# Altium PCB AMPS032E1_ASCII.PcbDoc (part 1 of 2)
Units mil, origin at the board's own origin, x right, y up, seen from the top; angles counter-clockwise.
Board outline 1650 x 2660 mil, 4 copper layers (Top Layer L1, GND Plane L2, VCC/VEE Plane L3, Bottom Layer L4), stack 61.6 mil thick; 53 components, 15 nets, 89 pads, 109 vias.
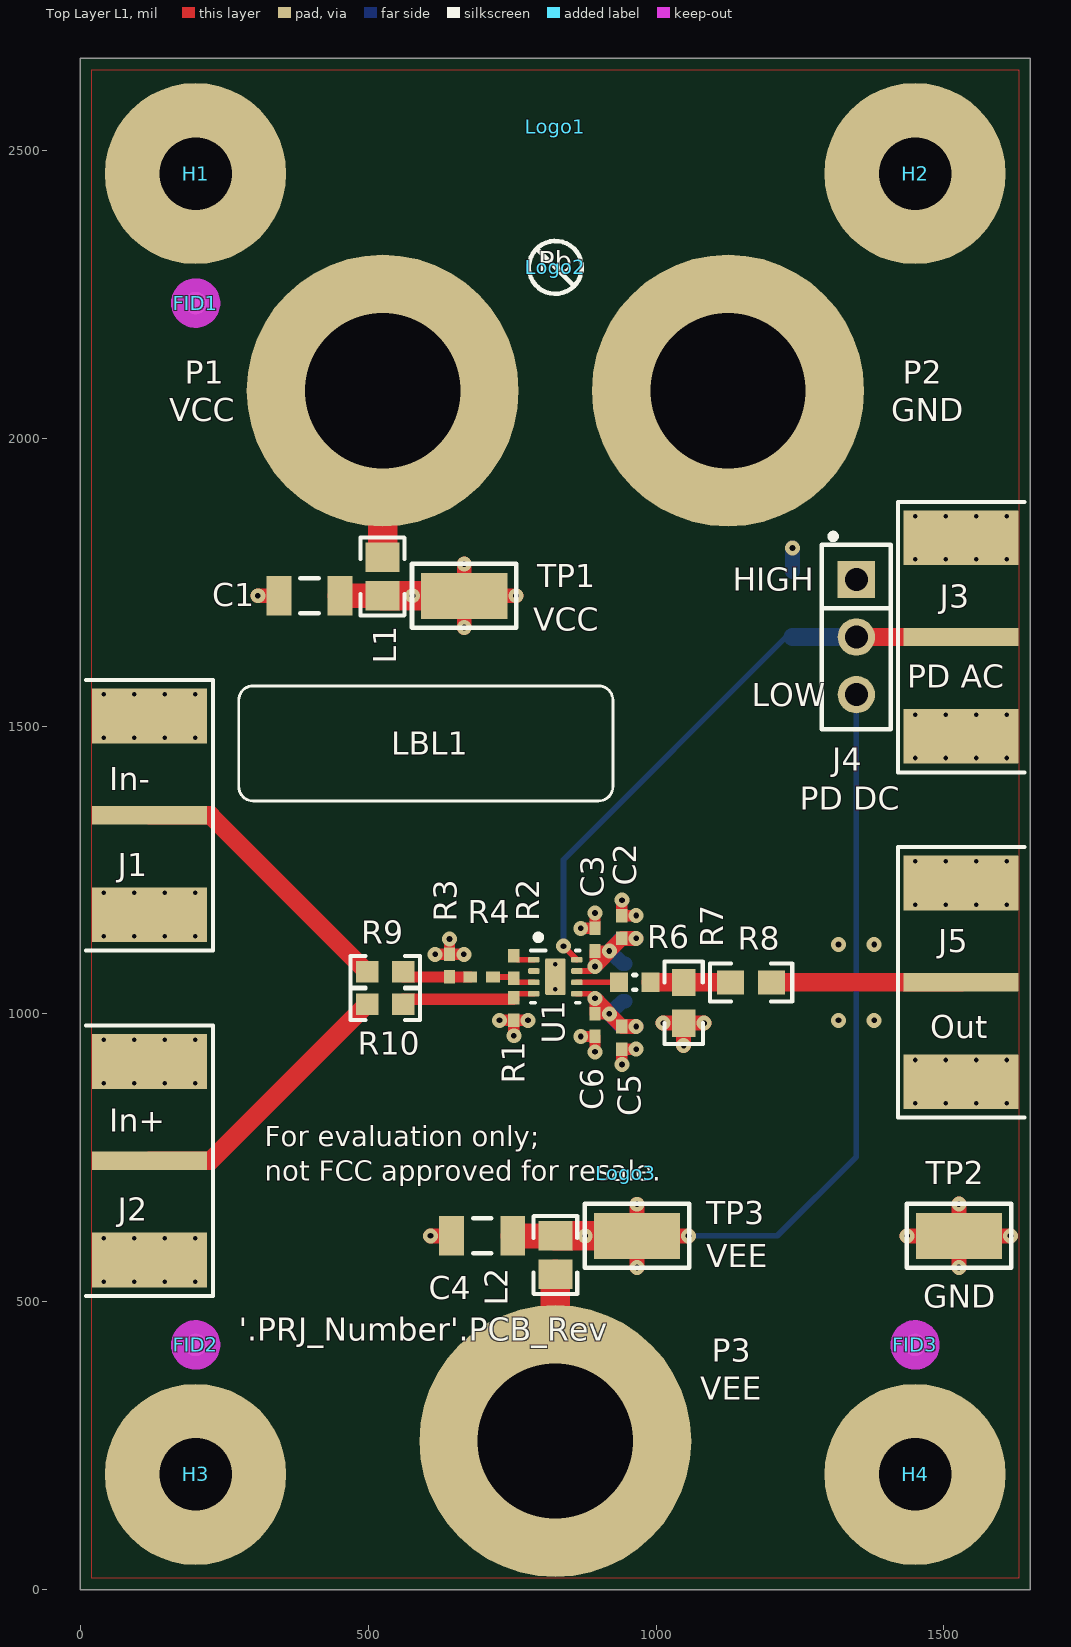
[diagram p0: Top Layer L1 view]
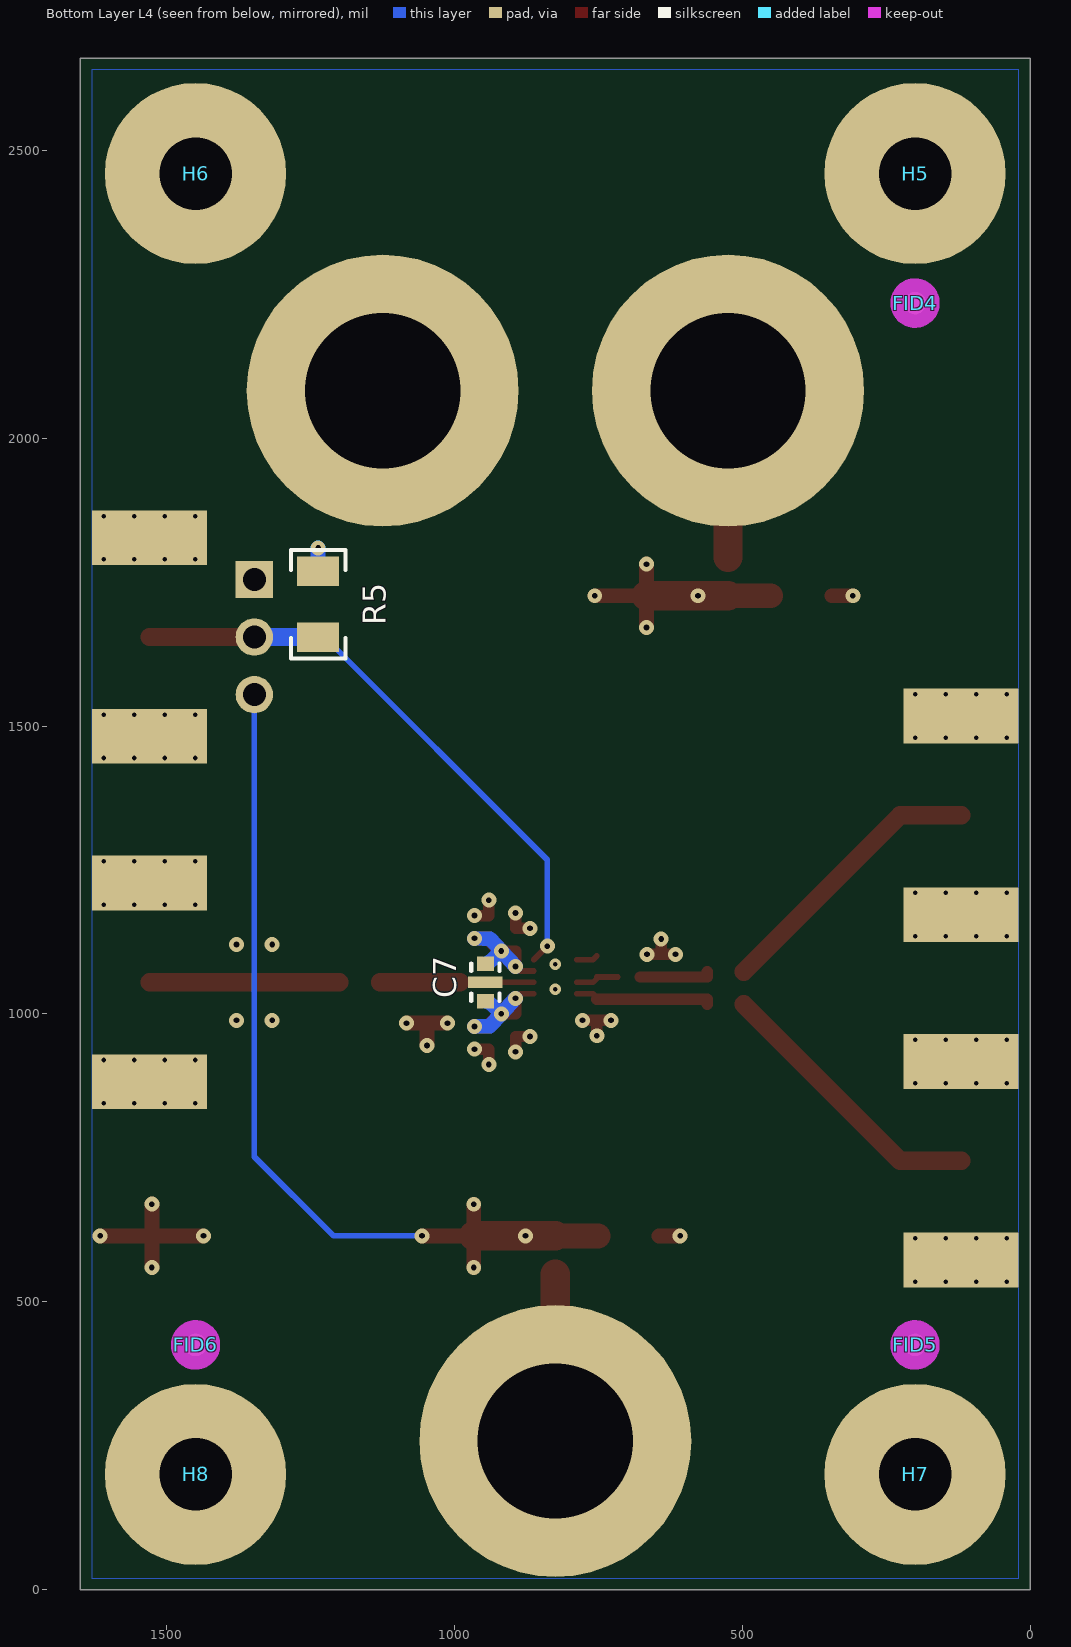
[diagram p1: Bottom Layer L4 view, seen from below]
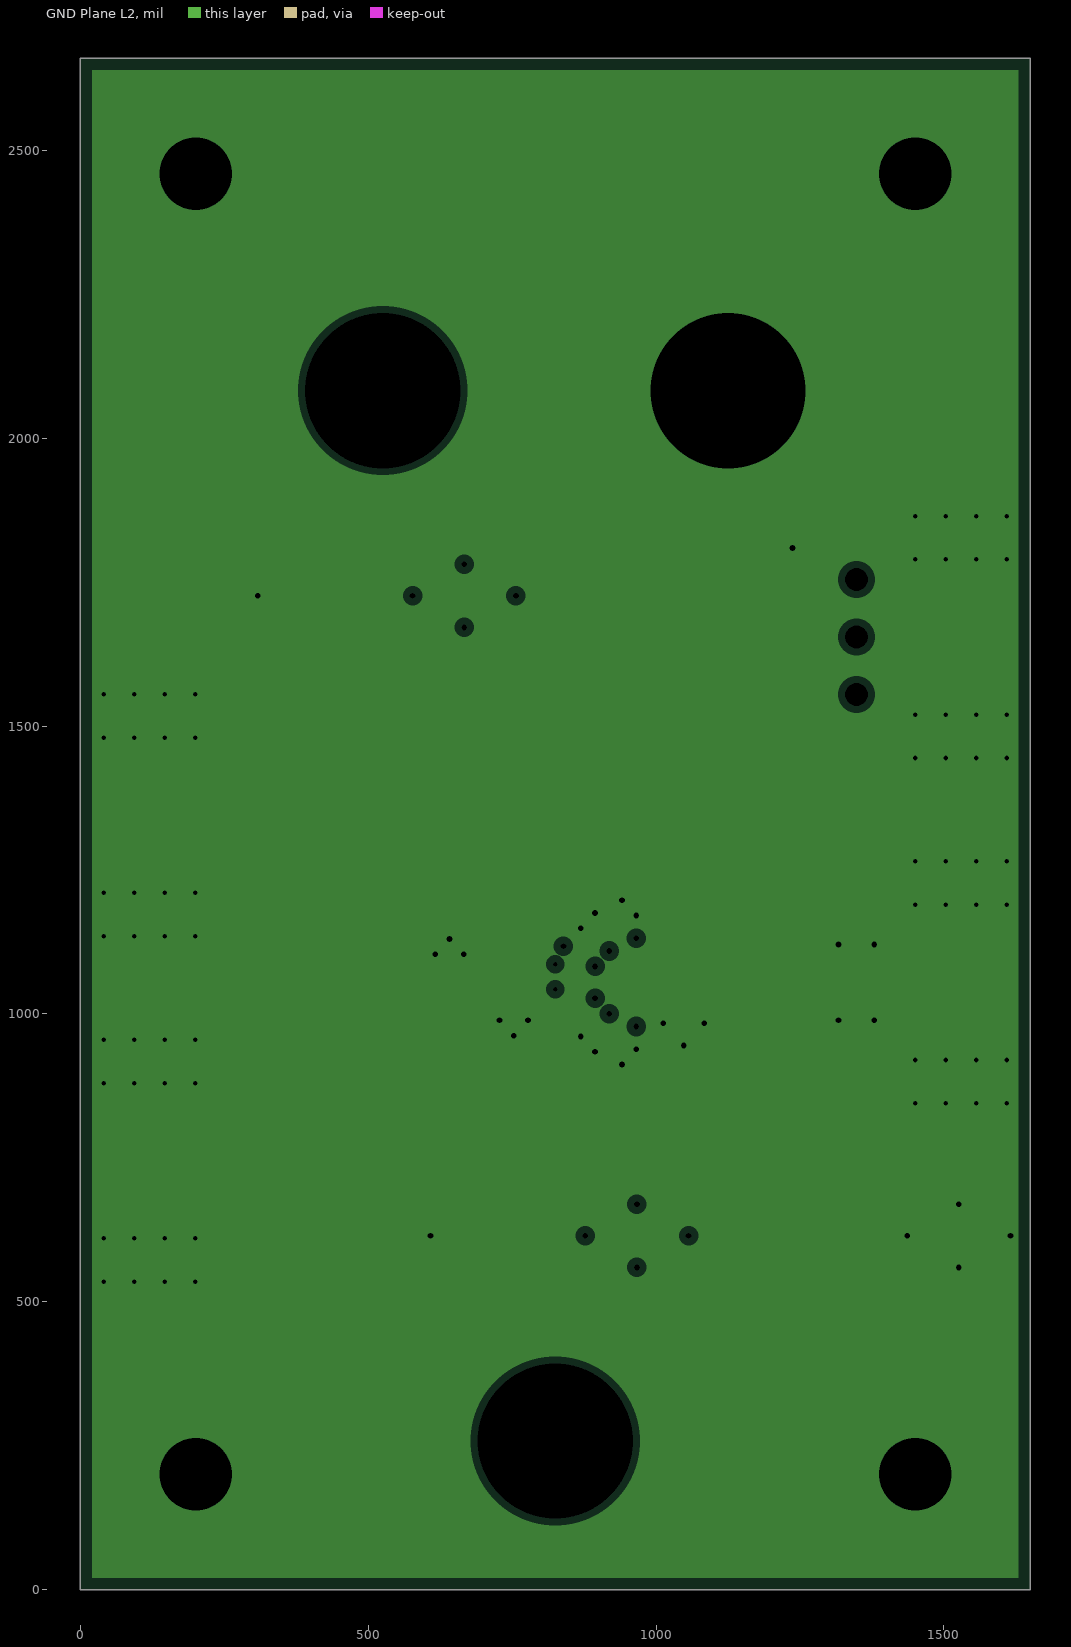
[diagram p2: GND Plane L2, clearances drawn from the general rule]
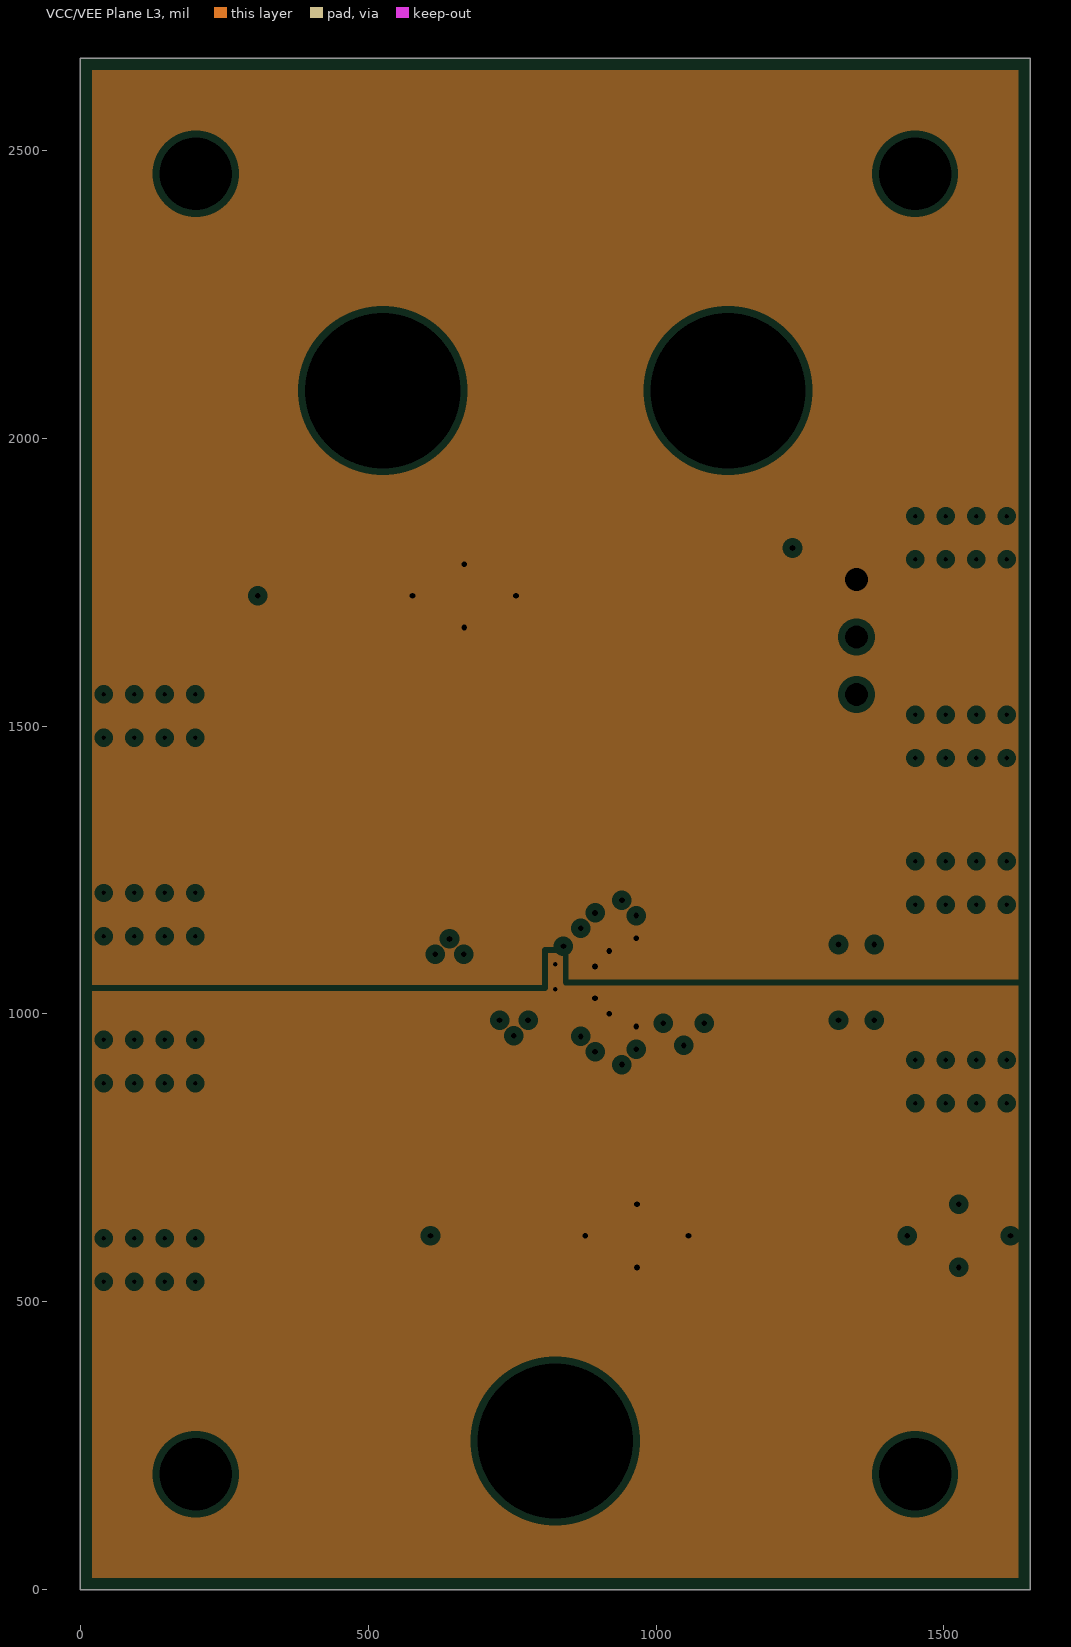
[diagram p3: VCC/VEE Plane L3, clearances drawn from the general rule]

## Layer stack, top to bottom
Top Solder: solder mask 0.4, Solder Resist, Dk 3.5
Top Layer L1: signal copper 1.4
Dielectric 1: core 15, FR408HR, Dk 3.8
GND Plane L2: plane copper 1.4, net GND
Dielectric 2: prepreg 26, FR-4 High Tg, Dk 4.6
VCC/VEE Plane L3: plane copper 1.4, net (Multiple Nets)
Dielectric 3: core 15, FR-4 High Tg, Dk 4.6
Bottom Layer L4: signal copper 1.4
Bottom Solder: solder mask 0.4, Solder Resist, Dk 3.5

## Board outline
0,0 1650,0 1650,2660 0,2660

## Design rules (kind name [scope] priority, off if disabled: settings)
AcuteAngle [All] p0: scope1count=1 scope1_0_kind=Board scope1_0_value=Board scope2count=1 scope2_0_kind=Board scope2_0_value=Board commentlength=0 minimum=4.50000000000000E+0001
AcuteAngle [All] p1: minimum=4.50000000000000E+0001 checktracksonly=FALSE
AssemblyTestPointUsage [All] p0: scope1count=1 scope1_0_kind=Board scope1_0_value=Board scope2count=1 scope2_0_kind=Board scope2_0_value=Board commentlength=0
AssemblyTestPointUsage [All] p1: valid=2
AssemblyTestpoint [All] p0: scope1count=1 scope1_0_kind=Board scope1_0_value=Board scope2count=1 scope2_0_kind=Board scope2_0_value=Board commentlength=0
BoardOutlineClearance BoardOutlineClearance_MountingHoles [All] p0 off: scope1count=1 scope1_0_kind=Board scope1_0_value=Board scope2count=1 scope2_0_kind=Board scope2_0_value=Board commentlength=86 gap=40 // Protel DXP Scope 1 Expression Was: OnCopper and InComponentClass('Mounting Holes')
BoardOutlineClearance BoardOutlineClearance_Poly [All] p0 off: scope1count=1 scope1_0_kind=Board scope1_0_value=Board scope2count=1 scope2_0_kind=Board scope2_0_value=Board commentlength=58 gap=20 // Protel DXP Scope 1 Expression Was: OnCopper and IsPoly
BoardOutlineClearance [All] p0 off: scope1count=1 scope1_0_kind=Board scope1_0_value=Board scope2count=1 scope2_0_kind=Board scope2_0_value=Board commentlength=172 gap=20 // Protel DXP Scope 1 Expression Was: OnCopper and Not InComponentClass('Logo') and not InComponentClass('FiducialMark') and not InRegion(1000,500,4000,800) and not InPoly
BoardOutlineClearance BoardOutlineClearance_MountingHoles [OnCopper and InComponentClass('Mounting Holes')] p1: gap=40 ignorepadtopadclearanceinfootprint=FALSE
BoardOutlineClearance BoardOutlineClearance_Poly [OnCopper and IsPoly] p2: gap=20 ignorepadtopadclearanceinfootprint=FALSE
BoardOutlineClearance [OnCopper and Not InComponentClass('Logo') and not InComponentClass('FiducialMark') and not InRegion(1000,500,4000,800) and not InPoly] p3: gap=20 ignorepadtopadclearanceinfootprint=FALSE
Clearance Clearance_FiducialMark [All] p0 off: scope1count=1 scope1_0_kind=Board scope1_0_value=Board scope2count=1 scope2_0_kind=Board scope2_0_value=Board commentlength=81 gap=0 // Protel DXP Scope 2 Expression Was: IsPad and InComponentClass('FiducialMark')
Clearance Clearance_1 [All] p0 off: scope1count=1 scope1_0_kind=Board scope1_0_value=Board scope2count=1 scope2_0_kind=Board scope2_0_value=Board commentlength=137 gap=35 // Protel DXP Scope 2 Expression Was: (InNet('NetJ1_1') OR InNet('NetJ2_1') OR InNet('NetJ4_2') OR InNet('NetJ5_1') OR InNet('NetR6_*'))
Clearance Clearance_Keepouts [All] p0 off: scope1count=1 scope1_0_kind=Board scope1_0_value=Board scope2count=1 scope2_0_kind=Board scope2_0_value=Board commentlength=99 gap=0 // Protel DXP Scope 2 Expression Was: ((IsTrack Or IsArc) And Not InPoly) And IsFree and IsKeepOut
Clearance Clearance_Poly [All] p0 off: scope1count=1 scope1_0_kind=Board scope1_0_value=Board scope2count=1 scope2_0_kind=Board scope2_0_value=Board commentlength=48 gap=13 // Protel DXP Scope 1 Expression Was: InPolygon
Clearance [All] p0: scope1count=1 scope1_0_kind=Board scope1_0_value=Board scope2count=1 scope2_0_kind=Board scope2_0_value=Board commentlength=0 gap=7.87
Clearance Clearance_FiducialMark [IsKeepOut and InComponentClass('FiducialMark') vs IsPad and InComponentClass('FiducialMark')] p1: gap=0 ignorepadtopadclearanceinfootprint=FALSE
Clearance Clearance_1 [(InNamedPolygon('Top Layer L1-GND')) vs (InNet('NetJ1_1') OR InNet('NetJ2_1') OR InNet('NetJ4_2') OR InNet('NetJ5_1') OR InNet('NetR6_*'))] p2: gap=35 ignorepadtopadclearanceinfootprint=FALSE except(0: Arc-Hole Track-Hole SMDPad-Hole THPad-Hole Via-Hole Fill-Hole Poly-Hole Region-Hole Text-Hole)
Clearance Clearance_Keepouts [((IsTrack Or IsArc) And Not InPoly) And IsFree and IsKeepOut vs ((IsTrack Or IsArc) And Not InPoly) And IsFree and IsKeepOut] p3: gap=0 ignorepadtopadclearanceinfootprint=FALSE
Clearance Clearance_Poly [InPolygon] p4: gap=13 ignorepadtopadclearanceinfootprint=FALSE except(0: Arc-Hole Track-Hole SMDPad-Hole THPad-Hole Via-Hole Fill-Hole Poly-Hole Region-Hole Text-Hole)
Clearance [All] p5: gap=7.87 ignorepadtopadclearanceinfootprint=FALSE except(0: Arc-Hole Track-Hole SMDPad-Hole THPad-Hole Via-Hole Fill-Hole Poly-Hole Region-Hole Text-Hole)
ComponentClearance ComponentClearance_MountingHoles_FiducialMarks [All] p0: scope1count=1 scope1_0_kind=ComponentClass scope1_0_value="Mounting Holes" scope2count=1 scope2_0_kind=ComponentClass scope2_0_value=FiducialMark commentlength=0 gap=50 collisioncheckmode=3
ComponentClearance ComponentClearance_Shunt [All] p0: scope1count=1 scope1_0_kind=ComponentClass scope1_0_value=Header scope2count=1 scope2_0_kind=ComponentClass scope2_0_value=Shunt commentlength=0 gap=0 collisioncheckmode=3
ComponentClearance ComponentClearance_Logo [All] p0: scope1count=1 scope1_0_kind=ComponentClass scope1_0_value=Logo scope2count=1 scope2_0_kind=Board scope2_0_value=Board commentlength=0 gap=50 collisioncheckmode=3
ComponentClearance ComponentClearance_ScrewToNut [All] p0 off: scope1count=1 scope1_0_kind=Board scope1_0_value=Board scope2count=1 scope2_0_kind=Board scope2_0_value=Board commentlength=71 gap=5 collisioncheckmode=3 // Protel DXP Scope 2 Expression Was: (HasFootprint('Keystone_1902C'))
ComponentClearance ComponentClearance_MountingHoles [All] p0: scope1count=1 scope1_0_kind=ComponentClass scope1_0_value="Mounting Holes" scope2count=1 scope2_0_kind=Board scope2_0_value=Board commentlength=0 gap=100 collisioncheckmode=3
ComponentClearance ComponentClearance_SmallPassives [All] p0 off: scope1count=1 scope1_0_kind=Board scope1_0_value=Board scope2count=1 scope2_0_kind=Board scope2_0_value=Board commentlength=536 gap=14.96 collisioncheckmode=3 // Protel DXP Scope 2 Expression Was: HasFootprint('0201*') or HasFootprint('0402*') or HasFootprint('0508') or HasFootprint('0603*') or HasFootprint('0612') or HasFootprint('0805*') or HasFootprint('0815*') or HasFootprint('0830*') or HasFootprint('1206*') or HasFootprint('1210*') or HasFootprint('1808*') or HasFootprint('1812*') or HasFootprint('1825*') or HasFootprint('2010*') or HasFootprint('2220*') or HasFootprint('2225*') or HasFootprint('2512*') or HasFootprint('2728*') or HasFootprint('3518*') or HasFootprint('DSG0008A')
ComponentClearance ComponentClearance_THtoSMT [All] p0 off: scope1count=1 scope1_0_kind=Board scope1_0_value=Board scope2count=1 scope2_0_kind=Board scope2_0_value=Board commentlength=53 gap=25 collisioncheckmode=3 // Protel DXP Scope 2 Expression Was: IsSMTComponent
ComponentClearance ComponentClearance_THtoTH [All] p0 off: scope1count=1 scope1_0_kind=Board scope1_0_value=Board scope2count=1 scope2_0_kind=Board scope2_0_value=Board commentlength=54 gap=30 collisioncheckmode=3 // Protel DXP Scope 2 Expression Was: IsThruComponent
ComponentClearance [All] p0: scope1count=1 scope1_0_kind=Board scope1_0_value=Board scope2count=1 scope2_0_kind=Board scope2_0_value=Board commentlength=0 gap=30 collisioncheckmode=3
ComponentClearance ComponentClearance_C8_R10 [All] p0 off: scope1count=1 scope1_0_kind=Board scope1_0_value=Board scope2count=1 scope2_0_kind=Board scope2_0_value=Board commentlength=80 gap=0 collisioncheckmode=3 // Protel DXP Scope 2 Expression Was: (InComponent('C8') OR InComponent('R10'))
ComponentClearance ComponentClearance_C9_R11 [All] p0 off: scope1count=1 scope1_0_kind=Board scope1_0_value=Board scope2count=1 scope2_0_kind=Board scope2_0_value=Board commentlength=80 gap=0 collisioncheckmode=3 // Protel DXP Scope 2 Expression Was: (InComponent('C9') OR InComponent('R11'))
ComponentClearance ComponentClearance_C8_R10 [(InComponent('C8') OR InComponent('R10')) vs (InComponent('C8') OR InComponent('R10'))] p1: gap=0 collisioncheckmode=3 verticalgap=0 showdistances=FALSE
ComponentClearance ComponentClearance_C9_R11 [(InComponent('C9') OR InComponent('R11')) vs (InComponent('C9') OR InComponent('R11'))] p2: gap=0 collisioncheckmode=3 verticalgap=0 showdistances=FALSE
ComponentClearance ComponentClearance_MountingHoles_FiducialMarks [InComponentClass('Mounting Holes') vs InComponentClass('FiducialMark')] p3: gap=50 collisioncheckmode=3 verticalgap=10 showdistances=FALSE
ComponentClearance ComponentClearance_Shunt [InComponentClass('Header') vs InComponentClass('Shunt')] p4: gap=0 collisioncheckmode=3 verticalgap=0 showdistances=FALSE
ComponentClearance ComponentClearance_Logo [InComponentClass('Logo')] p5: gap=50 collisioncheckmode=3 verticalgap=10 showdistances=FALSE
ComponentClearance ComponentClearance_ScrewToNut [(HasFootprint('NY PMS 440 0025 PH')) vs (HasFootprint('Keystone_1902C'))] p6: gap=5 collisioncheckmode=3 verticalgap=10 showdistances=FALSE
ComponentClearance ComponentClearance_MountingHoles [InComponentClass('Mounting Holes')] p7: gap=100 collisioncheckmode=3 verticalgap=100000 showdistances=FALSE
ComponentClearance ComponentClearance_SmallPassives [HasFootprint('0201*') or HasFootprint('0402*') or HasFootprint('0508') or HasFootprint('0603*') or HasFootprint('0612') or HasFootprint('0805*') or HasFootprint('0815*') or HasFootprint('0830*') or HasFootprint('1206*') or HasFootprint('1210*') or HasFootprint('1808*') or HasFootprint('1812*') or HasFootprint('1825*') or HasFootprint('2010*') or HasFootprint('2220*') or HasFootprint('2225*') or HasFootprint('2512*') or HasFootprint('2728*') or HasFootprint('3518*') or HasFootprint('DSG0008A') vs HasFootprint('0201*') or HasFootprint('0402*') or HasFootprint('0508') or HasFootprint('0603*') or HasFootprint('0612') or HasFootprint('0805*') or HasFootprint('0815*') or HasFootprint('0830*') or HasFootprint('1206*') or HasFootprint('1210*') or HasFootprint('1808*') or HasFootprint('1812*') or HasFootprint('1825*') or HasFootprint('2010*') or HasFootprint('2220*') or HasFootprint('2225*') or HasFootprint('2512*') or HasFootprint('2728*') or HasFootprint('3518*') or HasFootprint('DSG0008A')] p8: gap=14.96 collisioncheckmode=3 verticalgap=10 showdistances=FALSE
ComponentClearance ComponentClearance_THtoSMT [IsThruComponent vs IsSMTComponent] p9: gap=25 collisioncheckmode=3 verticalgap=30 showdistances=FALSE
ComponentClearance ComponentClearance_THtoTH [IsThruComponent vs IsThruComponent] p10: gap=30 collisioncheckmode=3 verticalgap=30 showdistances=FALSE
ComponentClearance [All] p11: gap=30 collisioncheckmode=3 verticalgap=10 showdistances=FALSE
DiffPairsRouting [All] p0: scope1count=1 scope1_0_kind=Board scope1_0_value=Board scope2count=1 scope2_0_kind=Board scope2_0_value=Board commentlength=0
DiffPairsRouting [All] p1: maxlimit=100 minlimit=10 mostfreqgap=10 toplayer_minwidth=15 toplayer_maxwidth=15 toplayer_prefwidth=15 bottomlayer_minwidth=15 bottomlayer_maxwidth=15 bottomlayer_prefwidth=15 maxuncoupledlength=1000
FabricationTestPointUsage TestPointUsage [All] p0: scope1count=1 scope1_0_kind=Board scope1_0_value=Board scope2count=1 scope2_0_kind=Board scope2_0_value=Board commentlength=0 valid=2 allowmultiple=FALSE
FabricationTestPointUsage TestPointUsage [All] p1: valid=2 allowmultiple=FALSE
FabricationTestpoint Testpoint [All] p0: scope1count=1 scope1_0_kind=Board scope1_0_value=Board scope2count=1 scope2_0_kind=Board scope2_0_value=Board commentlength=0 side=3 testpointundercomponent=TRUE minsize=40 maxsize=100 preferedsize=60 minholesize=0 maxholesize=40 preferedholesize=32 testpointgrid=1
FabricationTestpoint Testpoint [All] p1: side=3 testpointundercomponent=TRUE minsize=40 maxsize=100 preferedsize=60 minholesize=0 maxholesize=40 preferedholesize=32 testpointgrid=1 allowsidetop=TRUE allowsidebottom=TRUE usegrid=TRUE gridtolerance=0.01
FanoutControl Fanout_LCC [All] p0 off: scope1count=1 scope1_0_kind=Board scope1_0_value=Board scope2count=1 scope2_0_kind=Board scope2_0_value=Board commentlength=69 // Protel DXP Scope 1 Expression Was: IsLCC   Fanout_LCC (Default Rule)
FanoutControl Fanout_BGA [All] p0 off: scope1count=1 scope1_0_kind=Board scope1_0_value=Board scope2count=1 scope2_0_kind=Board scope2_0_value=Board commentlength=69 // Protel DXP Scope 1 Expression Was: IsBGA   Fanout_BGA (Default Rule)
FanoutControl Fanout_SOIC [All] p0 off: scope1count=1 scope1_0_kind=Board scope1_0_value=Board scope2count=1 scope2_0_kind=Board scope2_0_value=Board commentlength=71 // Protel DXP Scope 1 Expression Was: IsSOIC   Fanout_SOIC (Default Rule)
FanoutControl Fanout_Default [All] p0: scope1count=1 scope1_0_kind=Board scope1_0_value=Board scope2count=1 scope2_0_kind=Board scope2_0_value=Board commentlength=30 // Fanout_Default (Default Rule)
FanoutControl Fanout_Small [All] p0 off: scope1count=1 scope1_0_kind=Board scope1_0_value=Board scope2count=1 scope2_0_kind=Board scope2_0_value=Board commentlength=84 // Protel DXP Scope 1 Expression Was: (CompPinCount < 5)   Fanout_Small (Default Rule)
FanoutControl Fanout_LCC [IsLCC] p1: bgadir=Out bgaviamode=Centered fanoutstyle=Auto fanoutdirection=Alternating viagrid=1 // Fanout_LCC (Default Rule)
FanoutControl Fanout_BGA [IsBGA] p2: bgadir=Out bgaviamode=Centered fanoutstyle=Auto fanoutdirection=Alternating viagrid=1 // Fanout_BGA (Default Rule)
FanoutControl Fanout_Default [All] p4: bgadir=Out bgaviamode=Centered fanoutstyle=Auto fanoutdirection=Alternating viagrid=1 // Fanout_Default (Default Rule)
FanoutControl Fanout_Small [(CompPinCount < 5)] p5: bgadir=Out bgaviamode=Centered fanoutstyle=Auto fanoutdirection=OutThenIn viagrid=1 // Fanout_Small (Default Rule)
Height Height_D1 [All] p0: scope1count=1 scope1_0_kind=Component scope1_0_value=D1 scope2count=1 scope2_0_kind=Board scope2_0_value=Board commentlength=0
Height [All] p0: scope1count=1 scope1_0_kind=Board scope1_0_value=Board scope2count=1 scope2_0_kind=Board scope2_0_value=Board commentlength=0
Height Height_D1 [InComponent('D1')] p1: minheight=0 maxheight=1079 prefheight=500
Height [All] p2: minheight=0 maxheight=1000 prefheight=500
HoleSize [All] p0: scope1count=1 scope1_0_kind=Board scope1_0_value=Board scope2count=1 scope2_0_kind=Board scope2_0_value=Board commentlength=0 absolutevalues=TRUE maxlimit=270 minlimit=7.87 maxpercent=80.000 minpercent=20.000
HoleSize [All] p1: absolutevalues=TRUE maxlimit=270 minlimit=7.87 maxpercent=80.000 minpercent=20.000
HoleToHoleClearance [All] p0: scope1count=1 scope1_0_kind=Board scope1_0_value=Board scope2count=1 scope2_0_kind=Board scope2_0_value=Board commentlength=0
LayerPairs [All] p0: scope1count=1 scope1_0_kind=Board scope1_0_value=Board scope2count=1 scope2_0_kind=Board scope2_0_value=Board commentlength=0 enforce=TRUE
MinimumAnnularRing MinimumAnnularRing_1 [All] p0 off: scope1count=1 scope1_0_kind=Board scope1_0_value=Board scope2count=1 scope2_0_kind=Board scope2_0_value=Board commentlength=152 minimumring=5.91 // Protel DXP Scope 1 Expression Was: (InNamedUnion('Unions 9') or InNamedUnion('Unions 13') or InNamedUnion('Unions 14') or InNamedUnion('Unions 15'))
MinimumAnnularRing MinimumAnnularRing_ThermalPadVias [All] p0 off: scope1count=1 scope1_0_kind=Board scope1_0_value=Board scope2count=1 scope2_0_kind=Board scope2_0_value=Board commentlength=63 minimumring=5.91 // Protel DXP Scope 1 Expression Was: IsVia and InAnyComponent
MinimumAnnularRing [All] p0: scope1count=1 scope1_0_kind=Board scope1_0_value=Board scope2count=1 scope2_0_kind=Board scope2_0_value=Board commentlength=0 minimumring=8
MinimumAnnularRing MinimumAnnularRing_1 [(InNamedUnion('Unions 9') or InNamedUnion('Unions 13') or InNamedUnion('Unions 14') or InNamedUnion('Unions 15'))] p1: minimumring=5.91
MinimumAnnularRing MinimumAnnularRing_ThermalPadVias [IsVia and InAnyComponent] p2: minimumring=5.91
MinimumAnnularRing [All] p3: minimumring=8
MinimumSolderMaskSliver MinimumSolderMaskSliver_Logo [All] p0: scope1count=1 scope1_0_kind=ComponentClass scope1_0_value=Logo scope2count=1 scope2_0_kind=ComponentClass scope2_0_value=Logo commentlength=0
MinimumSolderMaskSliver [All] p0: scope1count=1 scope1_0_kind=Board scope1_0_value=Board scope2count=1 scope2_0_kind=Board scope2_0_value=Board commentlength=0
MinimumSolderMaskSliver MinimumSolderMaskSliver_Logo [InComponentClass('Logo') vs InComponentClass('Logo')] p1: minsoldermaskwidth=0.7
MinimumSolderMaskSliver [All] p2: minsoldermaskwidth=3.94
NetAntennae [All] p0: scope1count=1 scope1_0_kind=Board scope1_0_value=Board scope2count=1 scope2_0_kind=Board scope2_0_value=Board commentlength=0
PasteMaskExpansion [All] p0: scope1count=1 scope1_0_kind=Board scope1_0_value=Board scope2count=1 scope2_0_kind=Board scope2_0_value=Board commentlength=0 expansion=0
PlaneClearance [All] p0: scope1count=1 scope1_0_kind=Board scope1_0_value=Board scope2count=1 scope2_0_kind=Board scope2_0_value=Board commentlength=0 clearance=12
PlaneClearance [All] p1: clearance=12
PlaneConnect [All] p0: scope1count=1 scope1_0_kind=Board scope1_0_value=Board scope2count=1 scope2_0_kind=Board scope2_0_value=Board commentlength=0 planeconnectstyle=Direct reliefexpansion=10 reliefentries=4 reliefconductorwidth=10 reliefairgap=10
PlaneConnect [All] p1: planeconnectstyle=Direct reliefexpansion=10 reliefentries=4 reliefconductorwidth=10 reliefairgap=10
PolygonConnect [All] p0: scope1count=1 scope1_0_kind=Board scope1_0_value=Board scope2count=1 scope2_0_kind=Board scope2_0_value=Board commentlength=0 connectstyle=Direct reliefconductorwidth=25 reliefentries=4 polygonreliefangle="90 Angle"
PolygonConnect [All] p1: connectstyle=Direct reliefconductorwidth=25 reliefentries=4 polygonreliefangle="90 Angle" airgapwidth=10
RoutingCorners [All] p0: scope1count=1 scope1_0_kind=Board scope1_0_value=Board scope2count=1 scope2_0_kind=Board scope2_0_value=Board commentlength=0 cornerstyle=45-Degree minsetback=100 maxsetback=100
RoutingLayers [All] p0: scope1count=1 scope1_0_kind=Board scope1_0_value=Board scope2count=1 scope2_0_kind=Board scope2_0_value=Board commentlength=0 top layer=Automatic bottom layer=Automatic
RoutingPriority [All] p0: scope1count=1 scope1_0_kind=Board scope1_0_value=Board scope2count=1 scope2_0_kind=Board scope2_0_value=Board commentlength=0
RoutingTopology [All] p0: scope1count=1 scope1_0_kind=Board scope1_0_value=Board scope2count=1 scope2_0_kind=Board scope2_0_value=Board commentlength=0 topology=Shortest
RoutingVias RoutingVias_1 [All] p0 off: scope1count=1 scope1_0_kind=Board scope1_0_value=Board scope2count=1 scope2_0_kind=Board scope2_0_value=Board commentlength=152 holewidth=28 width=50 viastyle="Through Hole" minholewidth=7.87 minwidth=19.68 maxholewidth=28 maxwidth=50 // Protel DXP Scope 1 Expression Was: (InNamedUnion('Unions 9') or InNamedUnion('Unions 13') or InNamedUnion('Unions 14') or InNamedUnion('Unions 15'))
RoutingVias ThermalPadVias [All] p0 off: scope1count=1 scope1_0_kind=Board scope1_0_value=Board scope2count=1 scope2_0_kind=Board scope2_0_value=Board commentlength=63 holewidth=7.87 width=19.68 viastyle="Through Hole" minholewidth=7.87 minwidth=19.68 maxholewidth=12.99 maxwidth=23.62 // Protel DXP Scope 1 Expression Was: IsVia and InAnyComponent
RoutingVias [All] p0: scope1count=1 scope1_0_kind=Board scope1_0_value=Board scope2count=1 scope2_0_kind=Board scope2_0_value=Board commentlength=0 holewidth=16 width=34 viastyle="Through Hole" minholewidth=7.87 minwidth=26 maxholewidth=40 maxwidth=65
RoutingVias RoutingVias_1 [(InNamedUnion('Unions 9') or InNamedUnion('Unions 13') or InNamedUnion('Unions 14') or InNamedUnion('Unions 15'))] p1: holewidth=28 width=50 viastyle="Through Hole" minholewidth=7.87 minwidth=19.68 maxholewidth=28 maxwidth=50
RoutingVias ThermalPadVias [IsVia and InAnyComponent] p2: holewidth=7.87 width=19.68 viastyle="Through Hole" minholewidth=7.87 minwidth=19.68 maxholewidth=12.99 maxwidth=23.62
RoutingVias [All] p3: holewidth=16 width=34 viastyle="Through Hole" minholewidth=7.87 minwidth=26 maxholewidth=40 maxwidth=65
ShortCircuit [All] p0: scope1count=1 scope1_0_kind=Board scope1_0_value=Board scope2count=1 scope2_0_kind=Board scope2_0_value=Board commentlength=0 allowed=FALSE
SilkToBoardRegionClearance [All] p0 off: scope1count=1 scope1_0_kind=Board scope1_0_value=Board scope2count=1 scope2_0_kind=Board scope2_0_value=Board commentlength=130 // Protel DXP Scope 1 Expression Was: Not ((IsComment or IsDesignator) And (Hide <> 'False')) and not InRegion(1000,500,4000,800)
SilkToBoardRegionClearance [Not ((IsComment or IsDesignator) And (Hide <> 'False')) and not InRegion(1000,500,4000,800)] p1:
SilkToSilkClearance SilkToSilkClearance_Pb-FreeLogo [All] p0 off: scope1count=1 scope1_0_kind=Board scope1_0_value=Board scope2count=1 scope2_0_kind=Board scope2_0_value=Board commentlength=120 // Protel DXP Scope 2 Expression Was: (HasFootprint('Pb-Free_Overlay_Medium') OR HasFootprint('Pb-Free_Overlay_Small'))
SilkToSilkClearance [All] p0: scope1count=1 scope1_0_kind=Board scope1_0_value=Board scope2count=1 scope2_0_kind=Board scope2_0_value=Board commentlength=0
SilkToSilkClearance SilkToSilkClearance_Pb-FreeLogo [(HasFootprint('Pb-Free_Overlay_Medium') OR HasFootprint('Pb-Free_Overlay_Small')) vs (HasFootprint('Pb-Free_Overlay_Medium') OR HasFootprint('Pb-Free_Overlay_Small'))] p1: silktosilkclearance=0
SilkToSilkClearance [All] p2: silktosilkclearance=4
SilkToSolderMaskClearance SilkToComponentPadClearance [All] p0 off: scope1count=1 scope1_0_kind=Board scope1_0_value=Board scope2count=1 scope2_0_kind=Board scope2_0_value=Board commentlength=87 // Protel DXP Scope 1 Expression Was: (IsPad or IsFill or IsRegion) and InAnycomponent
SilkToSolderMaskClearance "Silk to Solder Mask Opening" [All] p0: scope1count=1 scope1_0_kind=Board scope1_0_value=Board scope2count=1 scope2_0_kind=Board scope2_0_value=Board commentlength=0
SilkToSolderMaskClearance SilkToComponentPadClearance [(IsPad or IsFill or IsRegion) and InAnycomponent] p1: minsilkscreentomaskgap=5 clearancetoexposedcopper=TRUE
SilkToSolderMaskClearance "Silk to Solder Mask Opening" [All] p2: minsilkscreentomaskgap=4 clearancetoexposedcopper=FALSE
SolderMaskExpansion [All] p0: scope1count=1 scope1_0_kind=Board scope1_0_value=Board scope2count=1 scope2_0_kind=Board scope2_0_value=Board commentlength=0 expansion=1.97
SolderMaskExpansion [All] p1: expansion=1.97
UnRoutedNet [All] p0: scope1count=1 scope1_0_kind=Board scope1_0_value=Board scope2count=1 scope2_0_kind=Board scope2_0_value=Board commentlength=0
UnpouredPolygon [All] p0: scope1count=1 scope1_0_kind=Board scope1_0_value=Board scope2count=1 scope2_0_kind=Board scope2_0_value=Board commentlength=0
Width [All] p0: scope1count=1 scope1_0_kind=Board scope1_0_value=Board scope2count=1 scope2_0_kind=Board scope2_0_value=Board commentlength=0 maxlimit=100 minlimit=6 preferedwidth=10
Width [All] p1: maxlimit=100 minlimit=6 preferedwidth=10 checkconnectedcopper=TRUE
13 further rules are at their usual default settings.

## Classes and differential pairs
component class Header: J4
component class Label: LBL1
component class AssemblyNote: ZZ1 ZZ2 ZZ3 ZZ4
component class FiducialMark: FID1 FID2 FID3 FID4 FID5 FID6
component class Logo: Logo1
component class "Mounting Holes": H1 H2 H3 H4

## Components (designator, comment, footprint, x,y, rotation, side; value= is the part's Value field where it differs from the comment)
C1 "GRM31MR71E225KA93L" 1206L 397.85,1726.53 r180 top
C2 "C1005X5R1E224M050BC" 0402L 940.63,1151.16 r90 top
C3 "GRM155R71E103KA01D" 0402L 894,1129.07 r90 top
C4 "GRM31MR71E225KA93L" 1206L 697.85,614.47 r0 top
C5 "C1005X5R1E224M050BC" 0402L 940.63,958.53 r90 top
C6 "GRM155R71E103KA01D" 0402L 894,980.61 r90 top
C7 "500X14W103MV4T" X2Y_0603 946.5,1054.84 r90 bottom
FID1 "Fiducial" Fiducial10-20 200,2235 r0 top
FID2 "Fiducial" Fiducial10-20 200,425 r0 top
FID3 "Fiducial" Fiducial10-20 1450,425 r0 top
FID4 "Fiducial" Fiducial10-20 200,2235 r0 bottom
FID5 "Fiducial" Fiducial10-20 200,425 r0 bottom
FID6 "Fiducial" Fiducial10-20 1450,425 r0 bottom
H1 "NY PMS 440 0025 PH" "NY PMS 440 0025 PH" 200,2460 r0 top locked
H2 "NY PMS 440 0025 PH" "NY PMS 440 0025 PH" 1450,2460 r0 top locked
H3 "NY PMS 440 0025 PH" "NY PMS 440 0025 PH" 200,200 r0 top locked
H4 "NY PMS 440 0025 PH" "NY PMS 440 0025 PH" 1450,200 r0 top locked
H5 "1902C" Keystone_1902C 200,2460 r180 bottom locked
H6 "1902C" Keystone_1902C 1450,2460 r180 bottom locked
H7 "1902C" Keystone_1902C 200,200 r180 bottom locked
H8 "1902C" Keystone_1902C 1450,200 r180 bottom locked
J1 "In-" Emerson_142-0701-851 10,1345 r90 top
J2 "In+" Emerson_142-0701-851 10,745 r90 top
J3 "PD AC" Emerson_142-0701-851 1640,1654.84 r270 top
J4 "PD DC" TSW-103-07-X-S 1348,1654.84 r270 top
J5 "Out" Emerson_142-0701-851 1640,1054.84 r270 top
L1 "BLM21AG102SN1D" 0805 525,1760 r270 top
L2 "BLM21AG102SN1D" 0805 825,581 r90 top
LBL1 "Size: 0.65\" x 0.20 \"" Label_650x200 600,1470 r0 top
Logo1 "Texas Instruments" TI_Stacked_Overlay_Small 825,2541 r0 top
Logo2 "Pb-Free Symbol" Pb-Free_Overlay_Small 825,2297 r0 top
Logo3 "FCC disclaimer" FCC_disclaimer 947,723 r0 top
P1 "VCC" Keystone_6095 525,2083 r0 top
P2 "GND" Keystone_6095 1125,2083 r0 top
P3 "VEE" Keystone_6095 825,258 r0 top
R1 "CRCW040249R9FKED" 0402L 752.88,1008.58 r90 top
R2 "CRCW0402402RFKED" 0402L 752.88,1081.42 r90 top
R3 "CRCW04020000Z0ED" 0402L 641.12,1083.96 r270 top
R4 "CRCW040266R5FKED" 0402L 697,1064.27 r0 top
R5 "CRCW120649R9FKEA" 1206 1237,1711.93 r270 bottom
R6 "CRCW0603169RFKEA" 0603L 963,1054.84 r0 top
R7 "CRCW060371R5FKEA" 0603M 1048,1019.41 r90 top
R8 "CRCW06030000Z0EA" 0603M 1165,1054.84 r0 top
R9 "CRCW06030000Z0EA" 0603 529.5,1073.13 r180 top
R10 "CRCW06030000Z0EA" 0603 529.5,1016.87 r180 top
TP1 "VCC" Keystone_5019 666.75,1726.54 r180 top
TP2 "GND" Keystone_5019 1526,614.47 r0 top
TP3 "VEE" Keystone_5019 966.75,614.46 r0 top
U1 "OPA852IDSG" DSG0008A 825,1064.68 r0 top
ZZ1 "This Assembly Note is for PCB labels only" AssemblyNoteLabel 185,3938 r0 top
ZZ2 "These assemblies are ESD sensitive, ESD precautions shall be observed." AssemblyNote 185,3829.11 r0 top
ZZ3 "These assemblies must be clean and free from flux and all contaminants. Use of no clean flux is not acceptable." AssemblyNote 185,3740.56 r0 top
ZZ4 "These assemblies must comply with workmanship standards IPC-A-610 Class 2, unless otherwise specified." AssemblyNote 185,3652 r0 top

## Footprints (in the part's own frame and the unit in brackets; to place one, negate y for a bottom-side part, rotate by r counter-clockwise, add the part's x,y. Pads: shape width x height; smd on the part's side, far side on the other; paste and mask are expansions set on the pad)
0402L [mm] "0402 from SM-752 data"
  rect 0.6x0.5 smd: 1(-0.5,0) 2(0.5,0)
0603 [mm] "0603 from SM-752 data"
  rect 1x0.95 smd: 1(-0.8,0) 2(0.8,0)
  silkscreen extent -1.52,-0.69 1.52,0.69
0603L [mm] "0603 from SM-752 data"
  rect 0.8x0.85 smd: 1(-0.7,0) 2(0.7,0)
  silkscreen extent -0.07,-0.33 0.07,0.33
0603M [mm] "0603 from SM-752 data"
  rect 1.2x1.05 smd: 1(-0.9,0) 2(0.9,0)
  silkscreen extent -1.82,-0.84 1.82,0.84
0805 [mm] "0805 from SM-752 data"
  rect 1.3x1.5 smd: 1(-0.85,0) 2(0.85,0)
  silkscreen extent -1.72,-0.97 1.72,0.97
1206 [mm] "1206 from SM-752 data"
  rect 1.3x1.85 smd: 1(-1.45,0) 2(1.45,0)
  silkscreen extent -2.4,-1.21 2.4,1.21
1206L [mm] "1206 from SM-752 data"
  rect 1.1x1.75 smd: 1(-1.35,0) 2(1.35,0)
  silkscreen extent -0.4,-0.77 0.4,0.77
AssemblyNote [mil] "Assembly Note"
AssemblyNoteLabel [mil] "Assembly Note for PCB Labels"
DSG0008A [mm] "SON, 8-Leads, Body 2x2mm, Pitch 0.5mm, Thermal Pad 1.6x0.9mm, TI Recommended"
  rrect40% 0.5x0.25 smd: 1(-0.95,0.75) 2(-0.95,0.25) 3(-0.95,-0.25) 4(-0.95,-0.75) 5(0.95,-0.75) 6(0.95,-0.25) 7(0.95,0.25) 8(0.95,0.75)
  rrect14% 0.9x0.7 on Top Paste: 9(0,-0.45) 9(0,0.45)
  rrect11% 0.9x1.6 smd paste-0.45: 9(0,0)
  silkscreen extent -1.07,-1.15 1.07,1.15
Emerson_142-0701-851 [mil] "Johnson Components"
  rect 32x200 smd: 1(0,-110)
  rect 95x200 smd: 2(-172.5,-110) 3(172.5,-110)
  rect 95x200 smd far side: 4(172.5,-110) 5(-172.5,-110)
  silkscreen extent -235,-220 235,0
FCC_disclaimer [mil]
Fiducial10-20 [mm]
  round 1 smd mask+0: 1(0,0)
  Top Layer L1 keep-out circle w1.178: c0,0 r0.5
Keystone_1902C [mil] "Hex Standoff, 4-40 threaded, nylon"
Keystone_5019 [mm] "Test Point, Miniature, SMT"
  rect 3.8x2.03 smd: 1(0,0)
  silkscreen extent -2.31,-1.42 2.31,1.42
Keystone_6095 [mm] "Banana Jack Uninsulated Standard Type"
  round 12 hole 6.858: 1(0,0)
Label_650x200 [mil] "Thermal Transfer Label"
  silkscreen extent -325,-100 325,100
"NY PMS 440 0025 PH" [mm] "4-40 nylon screw and mounting hole"
  round 8 hole 3.2: 1(0,0)
Pb-Free_Overlay_Small [mil]
  silkscreen extent -46,-46 46,46
TI_Stacked_Overlay_Small [mil]
TSW-103-07-X-S [mm] "Samtec Header, 100mil, 1x3"
  rect 1.65x1.65 hole 1.016: 1(-2.54,0)
  round 1.65 hole 1.016: 2(0,0) 3(2.54,0)
  silkscreen extent -4.57,-1.52 4.06,1.52
X2Y_0603 [mm]
  rect 0.64x0.76 smd: 1(-0.83,0) 2(0.83,0)
  rect 0.51x1.52 smd: 3(0,0)
  silkscreen extent -0.82,-0.63 0.82,0.63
